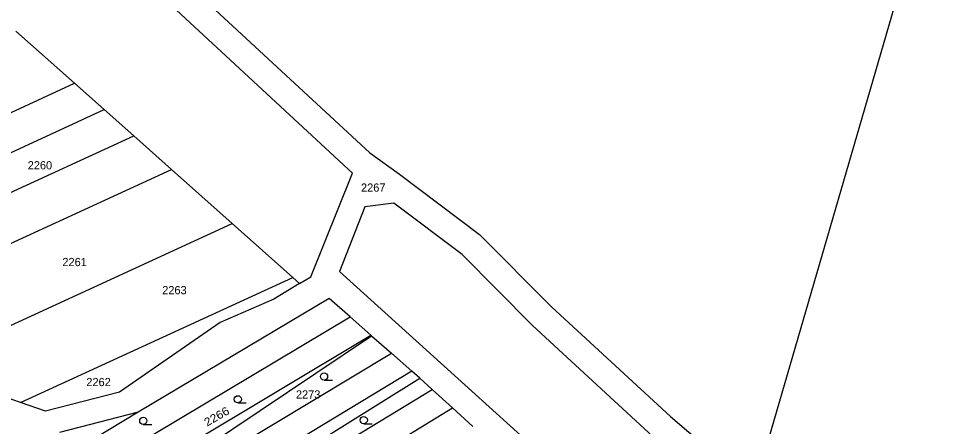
# Model space of a CAD drawing. Extents: x -606517 to -602431, y -1183120 to -1179397.
# Drawn here: x -605022.9 to -604831.4, y -1180706.6 to -1180622.1 of the extents above; entities that cross this region are included whole.
import ezdxf

# ---------------------------------------------------------------- set-up
doc = ezdxf.new("R2010")
doc.units = 0
doc.header["$LTSCALE"] = 0.68
doc.layers.add('1', color=7, linetype='Continuous', lineweight=25)
doc.layers.add('3', color=7, linetype='Continuous', lineweight=25)
doc.layers.add('2', color=7, linetype='Continuous')

msp = doc.modelspace()

# ---------------------------------------------------------------- linework, layer by layer
at = {"layer": '1'}
for p, q in [((-604870.51, -1180719.22), (-604831.4, -1180584.66)), ((-604989.5, -1180613.45), (-604950.2, -1180649.92)), ((-604953.77, -1180654.13), (-604993.72, -1180617.03)), ((-605023.45, -1180624.68), (-605011.3, -1180635.5)), ((-605068.31, -1180661.72), (-605011.3, -1180635.5)), ((-605011.3, -1180635.5), (-605005.17, -1180640.96)), ((-605062.78, -1180667.45), (-605005.17, -1180640.96)), ((-605005.17, -1180640.96), (-604999.05, -1180646.41)), ((-605057.57, -1180673.32), (-604999.05, -1180646.41)), ((-604999.05, -1180646.41), (-604991.23, -1180653.38)), ((-604950.2, -1180649.92), (-604944.05, -1180654.32)), ((-605050.64, -1180680.69), (-604991.23, -1180653.38)), ((-604991.23, -1180653.38), (-604978.67, -1180664.56)), ((-604962.41, -1180675.59), (-604953.77, -1180654.13)), ((-604944.05, -1180654.32), (-604927.43, -1180666.81)), ((-604945.2, -1180660.34), (-604951.19, -1180661.1)), ((-604931.06, -1180670.97), (-604945.2, -1180660.34)), ((-604951.19, -1180661.1), (-604956.42, -1180674.5)), ((-605038.77, -1180692.19), (-604978.67, -1180664.56)), ((-604978.67, -1180664.56), (-604966.14, -1180675.72)), ((-604927.43, -1180666.81), (-604912.51, -1180681.88)), ((-604916.47, -1180685.7), (-604931.06, -1180670.97)), ((-605022.49, -1180701.63), (-604966.14, -1180675.72)), ((-604966.14, -1180675.72), (-604964.72, -1180676.98)), ((-604964.72, -1180676.98), (-604962.41, -1180675.59)), ((-604956.42, -1180674.5), (-604836.32, -1180783.1)), ((-604964.72, -1180676.98), (-604970.02, -1180680.19)), ((-604958.58, -1180680.05), (-604998.1, -1180703.65)), ((-604970.02, -1180680.19), (-604981.13, -1180685.06)), ((-604954.27, -1180683.85), (-604958.58, -1180680.05)), ((-604912.51, -1180681.88), (-604887.93, -1180704.55)), ((-605012.78, -1180718.85), (-604954.27, -1180683.85)), ((-604954.27, -1180683.85), (-604949.95, -1180687.67)), ((-604981.13, -1180685.06), (-605001.99, -1180699.48)), ((-604891.57, -1180708.68), (-604916.47, -1180685.7)), ((-605008.53, -1180722.74), (-604949.95, -1180687.67)), ((-604949.95, -1180687.67), (-604949.79, -1180687.81)), ((-605005.73, -1180725.3), (-604949.79, -1180687.81)), ((-604949.79, -1180687.81), (-604945.7, -1180691.42)), ((-605004.28, -1180726.64), (-604945.7, -1180691.42)), ((-604945.7, -1180691.42), (-604941.48, -1180695.14)), ((-604941.48, -1180695.14), (-605000.04, -1180730.53)), ((-604939.85, -1180696.59), (-604941.48, -1180695.14)), ((-604997.71, -1180732.67), (-604939.85, -1180696.59)), ((-604939.85, -1180696.59), (-604937.27, -1180698.93)), ((-605022.49, -1180701.63), (-605032.71, -1180698.07)), ((-604995.77, -1180734.41), (-604937.27, -1180698.93)), ((-604937.27, -1180698.93), (-604933.06, -1180702.76)), ((-605001.99, -1180699.48), (-605017.34, -1180703.43)), ((-605017.34, -1180703.43), (-605022.49, -1180701.63)), ((-604991.49, -1180738.27), (-604933.06, -1180702.76)), ((-604933.06, -1180702.76), (-604928.82, -1180706.62)), ((-604998.1, -1180703.65), (-605017.03, -1180714.95)), ((-604998.1, -1180703.65), (-605014.41, -1180707.84)), ((-604887.93, -1180704.55), (-604872.6, -1180717.48))]:
    msp.add_line(p, q, dxfattribs=at)
at = {"layer": '3'}
for p, q in [((-604959.653, -1180696.98), (-604957.903, -1180696.98)), ((-604977.513, -1180701.71), (-604975.763, -1180701.71)), ((-604997.063, -1180706.17), (-604995.313, -1180706.17)), ((-604951.433, -1180706.01), (-604949.683, -1180706.01))]:
    msp.add_line(p, q, dxfattribs=at)
for centre in [(-604959.6529, -1180696.2298), (-604977.5129, -1180700.9598), (-604997.0629, -1180705.4198), (-604951.4329, -1180705.2598)]:
    msp.add_circle(centre, 0.75, dxfattribs=at)

# ---------------------------------------------------------------- texts
at = {"layer": '2'}
for s, p in [('2260', (-605021, -1180653.335)), ('2267', (-604951.99, -1180657.955)), ('2261', (-605013.82, -1180673.375)), ('2263', (-604993.15, -1180679.205)), ('2262', (-605008.86, -1180698.235)), ('2273', (-604965.46, -1180700.805))]:
    msp.add_text(s, height=1.7, dxfattribs=at).set_placement(p)
at = {"layer": '2', "width": 1.1}
msp.add_text('2266', height=1.7, rotation=30, dxfattribs=at).set_placement((-604983.867, -1180706.638))

doc.saveas('drawing.dxf')
